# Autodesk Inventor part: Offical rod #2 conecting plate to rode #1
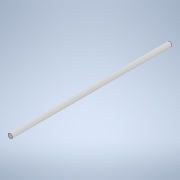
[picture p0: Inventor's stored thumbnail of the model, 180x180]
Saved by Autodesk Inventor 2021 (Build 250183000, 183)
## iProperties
Created: 2021-02
Part Number: Offical rod #2 conecting plate to rode #1
Material: Generic
Document SubType Name: Modeling
Designer: Owner
Density: 1 g/cm^3
Appearance: Default
Author: Owner
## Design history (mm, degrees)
sketch "Sketch1"
  geometry: C1 r 1.25 at (3.474, 0.982); 1 further point
  constraints: 1 centre point
  dimensions: "d0" = 2.5 dimension on point (0, 0) C1.centre C1; "d0" = 2.5 diameter of C1
extrude "Extrusion1" new body sketch "Sketch1" distance "d1" = 86; taper "d2" = 0 deg
body "Solid1"
